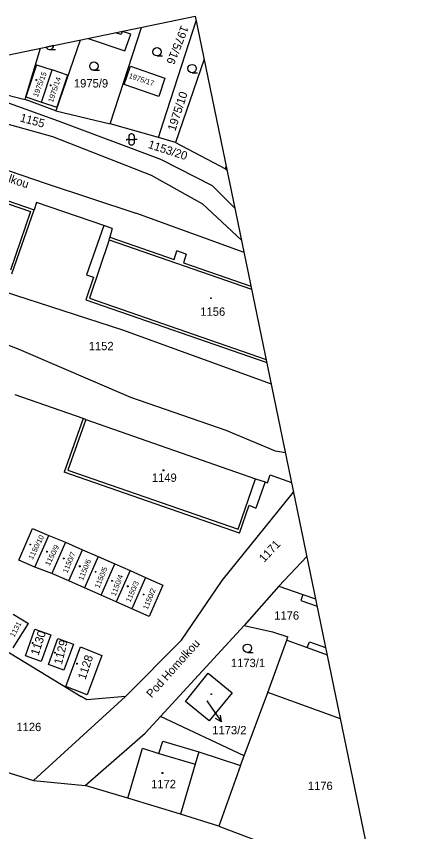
# Model space of a CAD drawing. Extents: x -804166 to -803706, y -1151030 to -1150147.
# Drawn here: x -803907.6 to -803833, y -1150293.8 to -1150147.3 of the extents above; entities that cross this region are included whole.
import ezdxf

# ---------------------------------------------------------------- set-up
doc = ezdxf.new("R2010")
doc.units = 0
for name, color, linetype in [('Default', 7, 'Continuous'), ('formát', 7, 'Continuous'), ('kn_celek - Cisla parcel pomocna', 7, 'Continuous'), ('kn_celek - Cisla pozemkovych parcel', 7, 'Continuous'), ('kn_celek - Cisla stavebnich parcel', 7, 'Continuous'), ('kn_celek - Dalsi prvky mapy popis', 7, 'Continuous'), ('kn_celek - Hranice parcel', 7, 'Continuous'), ('kn_celek - Vnitrni kresby', 7, 'Continuous'), ('kn_celek - Znacky budov', 7, 'Continuous'), ('kn_celek - Znacky kultur', 7, 'Continuous')]:
    doc.layers.add(name, color=color, linetype=linetype)

# ---------------------------------------------------------------- blocks, each defined once
blk = doc.blocks.new('316')
at = {"layer": 'Default'}
for p, q in [((-5, 15.5), (-5, 4.5)), ((0.5, 20), (-0.5, 20)), ((5, 4.5), (5, 15.5)), ((-8.3, 10), (-10, 8.1)), ((-5, 10), (-8.3, 10)), ((-5, 10), (5, 10)), ((-0.5, 0), (0.5, 0)), ((10, 10), (5, 10))]:
    blk.add_line(p, q, dxfattribs=at)
for centre, start, end in [((-0.5, 15.5), 90, 180), ((0.5, 15.5), 0, 90), ((-0.5, 4.5), 180, 270), ((0.5, 4.5), 270, 0)]:
    blk.add_arc(centre, 4.5, start, end, dxfattribs=at)
blk = doc.blocks.new('304')
at = {"layer": 'Default'}
blk.add_line((-0.1, 0), (9.9, 0), dxfattribs=at)
blk.add_circle((-0.1, 7.5), 7.5, dxfattribs=at)
blk = doc.blocks.new('402')
at = {"layer": 'Default'}
for p, q in [((-0.8, 0.8), (0.7, 0.8)), ((-0.8, 0.8), (-0.8, -0.7)), ((0.7, 0.8), (0.7, -0.7)), ((0.7, -0.7), (-0.8, -0.7))]:
    blk.add_line(p, q, dxfattribs=at)
blk = doc.blocks.new('Z61')
at = {"layer": 'Default'}
for p, q in [((0, 0), (30, 0)), ((30, 0), (19.2, 5.3)), ((30, 0), (19.2, -5.3))]:
    blk.add_line(p, q, dxfattribs=at)

msp = doc.modelspace()

# ---------------------------------------------------------------- linework, layer by layer
at = {"layer": 'Default'}
for p, q in [((-803900.82, -1150152.59), (-803902.24, -1150152.88)), ((-803901.57, -1150153.3), (-803900.57, -1150153.3))]:
    msp.add_line(p, q, dxfattribs=at)
msp.add_arc((-803901.57, -1150152.55), 0.75, 206.3406, 356.9897, dxfattribs=at)
at = {"layer": 'formát'}
for p, q in [((-804166.3, -1150207.4), (-803875.43, -1150147.35)), ((-803875.43, -1150147.35), (-803832.97, -1150353.01))]:
    msp.add_line(p, q, dxfattribs=at)
at = {"layer": 'kn_celek - Cisla parcel pomocna'}
msp.add_line((-803873.37, -1150270.26), (-803872.45, -1150271.59), dxfattribs=at)
at = {"layer": 'kn_celek - Hranice parcel'}
for p, q in [((-803881.15, -1150166.28), (-803875.27, -1150148.15)), ((-803890.73, -1150166.65), (-803885.1, -1150149.34)), ((-803887.03, -1150150.53), (-803888.49, -1150150.05)), ((-803888.07, -1150153.56), (-803887.03, -1150150.53)), ((-803896.11, -1150151.62), (-803900.48, -1150164.31)), ((-803894.68, -1150151.32), (-803888.07, -1150153.56)), ((-803904.55, -1150157.46), (-803903.24, -1150153.09)), ((-803873.84, -1150155.07), (-803879, -1150169.98)), ((-803903.93, -1150156.08), (-803905.85, -1150161.82)), ((-803903.93, -1150156.08), (-803901.16, -1150156.99)), ((-803903.08, -1150162.75), (-803901.16, -1150156.99)), ((-803898.39, -1150157.91), (-803901.16, -1150156.99)), ((-803888.2, -1150159.59), (-803887.07, -1150156.33)), ((-803887.07, -1150156.33), (-803880.91, -1150158.47)), ((-803905.85, -1150161.82), (-803904.55, -1150157.46)), ((-803898.39, -1150157.91), (-803900.31, -1150163.68)), ((-803880.91, -1150158.47), (-803881.98, -1150161.74)), ((-803881.98, -1150161.74), (-803888.2, -1150159.59)), ((-803899.99, -1150166.2), (-803915.47, -1150160.65)), ((-803912.36, -1150160.67), (-803906, -1150162.31)), ((-803906, -1150162.31), (-803905.85, -1150161.82)), ((-803900.48, -1150164.31), (-803906, -1150162.31)), ((-803905.85, -1150161.82), (-803903.08, -1150162.75)), ((-803903.08, -1150162.75), (-803900.31, -1150163.68)), ((-803900.48, -1150164.31), (-803890.73, -1150166.65)), ((-803915.16, -1150165.04), (-803901.06, -1150168.96)), ((-803881.62, -1150173.04), (-803899.99, -1150166.2)), ((-803882.07, -1150169.11), (-803890.73, -1150166.65)), ((-803882.07, -1150169.11), (-803881.15, -1150166.28)), ((-803901.06, -1150168.96), (-803883.37, -1150175.87)), ((-803879, -1150169.98), (-803882.07, -1150169.11)), ((-803879, -1150169.98), (-803870, -1150174.71)), ((-803919.23, -1150171.55), (-803902.24, -1150177.36)), ((-803872.35, -1150177.78), (-803881.62, -1150173.04)), ((-803870, -1150174.71), (-803869.87, -1150174.31)), ((-803883.37, -1150175.87), (-803874.13, -1150181)), ((-803870, -1150174.71), (-803869.75, -1150174.89)), ((-803902.24, -1150177.36), (-803886.14, -1150182.73)), ((-803868.32, -1150181.79), (-803872.35, -1150177.78)), ((-803912.9, -1150179.16), (-803904.38, -1150182.12)), ((-803903.94, -1150180.77), (-803904.38, -1150182.12)), ((-803891.87, -1150184.92), (-803903.94, -1150180.77)), ((-803874.13, -1150181), (-803867.13, -1150187.56)), ((-803908.4, -1150193.58), (-803904.38, -1150182.12)), ((-803866.67, -1150189.78), (-803886.14, -1150182.73)), ((-803891.87, -1150184.92), (-803894.99, -1150193.77)), ((-803890.34, -1150185.46), (-803891.87, -1150184.92)), ((-803890.34, -1150185.46), (-803890.78, -1150187.03)), ((-803890.78, -1150187.03), (-803879.25, -1150191.02)), ((-803879.25, -1150191.02), (-803878.76, -1150189.48)), ((-803877.06, -1150190.07), (-803878.76, -1150189.48)), ((-803877.06, -1150190.07), (-803877.56, -1150191.6)), ((-803877.56, -1150191.6), (-803865.43, -1150195.8)), ((-803893.69, -1150194.21), (-803895.12, -1150198.28)), ((-803894.99, -1150193.77), (-803893.69, -1150194.21)), ((-803907.04, -1150207.19), (-803936.79, -1150195.65)), ((-803909.95, -1150196.71), (-803888.51, -1150203.65)), ((-803895.12, -1150198.28), (-803862.59, -1150209.54)), ((-803888.51, -1150203.65), (-803861.8, -1150213.36)), ((-803887.03, -1150215.78), (-803907.04, -1150207.19)), ((-803895.6, -1150219.58), (-803907.76, -1150215.33)), ((-803869.9, -1150221.72), (-803887.03, -1150215.78)), ((-803895.6, -1150219.58), (-803898.96, -1150229.23)), ((-803895.12, -1150219.75), (-803895.6, -1150219.58)), ((-803895.12, -1150219.75), (-803864.59, -1150230.39)), ((-803861.03, -1150225.43), (-803869.9, -1150221.72)), ((-803859.25, -1150225.72), (-803861.03, -1150225.43)), ((-803867.5, -1150240.16), (-803898.96, -1150229.23)), ((-803862.45, -1150231.1), (-803861.96, -1150229.72)), ((-803861.96, -1150229.72), (-803858.15, -1150231.05)), ((-803864.59, -1150230.39), (-803862.9, -1150230.95)), ((-803862.9, -1150230.95), (-803864.54, -1150235.66)), ((-803862.9, -1150230.95), (-803862.45, -1150231.1)), ((-803870.63, -1150248.69), (-803857.79, -1150232.8)), ((-803867.5, -1150240.16), (-803865.74, -1150235.12)), ((-803865.74, -1150235.12), (-803864.54, -1150235.66)), ((-803907.14, -1150244.99), (-803904.65, -1150239.3)), ((-803904.65, -1150239.3), (-803901.77, -1150240.6)), ((-803904.26, -1150246.27), (-803901.77, -1150240.6)), ((-803901.77, -1150240.6), (-803898.77, -1150241.78)), ((-803898.77, -1150241.78), (-803901.18, -1150247.39)), ((-803898.77, -1150241.78), (-803895.71, -1150243.13)), ((-803898.17, -1150248.72), (-803895.71, -1150243.13)), ((-803895.71, -1150243.13), (-803892.87, -1150244.37)), ((-803892.87, -1150244.37), (-803895.33, -1150249.98)), ((-803892.87, -1150244.37), (-803889.9, -1150245.68)), ((-803860.43, -1150249.7), (-803855.41, -1150244.35)), ((-803904.26, -1150246.27), (-803907.14, -1150244.99)), ((-803901.18, -1150247.39), (-803904.26, -1150246.27)), ((-803892.37, -1150251.29), (-803889.9, -1150245.68)), ((-803889.9, -1150245.68), (-803887.16, -1150246.89)), ((-803898.17, -1150248.72), (-803901.18, -1150247.39)), ((-803887.16, -1150246.89), (-803889.62, -1150252.51)), ((-803887.16, -1150246.89), (-803884.36, -1150248.11)), ((-803895.33, -1150249.98), (-803898.17, -1150248.72)), ((-803884.36, -1150248.11), (-803886.83, -1150253.75)), ((-803884.36, -1150248.11), (-803881.25, -1150249.49)), ((-803877.93, -1150259.4), (-803870.63, -1150248.69)), ((-803892.37, -1150251.29), (-803895.33, -1150249.98)), ((-803881.25, -1150249.49), (-803883.72, -1150255.11)), ((-803860.43, -1150249.7), (-803866.67, -1150256.73)), ((-803860.43, -1150249.7), (-803856.1, -1150251.19)), ((-803889.62, -1150252.51), (-803892.37, -1150251.29)), ((-803856.1, -1150251.19), (-803856.47, -1150252.28)), ((-803886.83, -1150253.75), (-803889.62, -1150252.51)), ((-803856.47, -1150252.28), (-803853.56, -1150253.27)), ((-803908.17, -1150254.71), (-803905.37, -1150256.41)), ((-803883.72, -1150255.11), (-803886.83, -1150253.75)), ((-803908.13, -1150260.76), (-803905.37, -1150256.41)), ((-803916.86, -1150256.8), (-803895.91, -1150269.48)), ((-803905.91, -1150262.21), (-803904.24, -1150257.41)), ((-803904.24, -1150257.41), (-803901.39, -1150258.44)), ((-803881.7, -1150273.09), (-803866.67, -1150256.73)), ((-803866.67, -1150256.73), (-803861.59, -1150257.9)), ((-803861.59, -1150257.9), (-803858.81, -1150258.78)), ((-803901.39, -1150258.44), (-803903.13, -1150263.19)), ((-803901.78, -1150263.76), (-803900.12, -1150259.06)), ((-803900.12, -1150259.06), (-803897.31, -1150260.08)), ((-803888, -1150269.48), (-803877.93, -1150259.4)), ((-803862.41, -1150268.75), (-803858.98, -1150259.36)), ((-803858.98, -1150259.36), (-803858.81, -1150258.78)), ((-803858.98, -1150259.36), (-803855.32, -1150260.7)), ((-803897.31, -1150260.08), (-803899.02, -1150264.79)), ((-803898.69, -1150267.68), (-803896.04, -1150260.6)), ((-803896.04, -1150260.6), (-803892.24, -1150262.13)), ((-803855.32, -1150260.7), (-803854.92, -1150259.66)), ((-803854.92, -1150259.66), (-803852.03, -1150260.7)), ((-803903.13, -1150263.19), (-803905.91, -1150262.21)), ((-803892.24, -1150262.13), (-803894.87, -1150269.18)), ((-803899.02, -1150264.79), (-803901.78, -1150263.76)), ((-803877.21, -1150270.37), (-803873.13, -1150265.29)), ((-803873.13, -1150265.29), (-803868.81, -1150268.81)), ((-803894.87, -1150269.18), (-803898.69, -1150267.68)), ((-803904.51, -1150284.6), (-803888, -1150269.48)), ((-803894.93, -1150270.07), (-803895.91, -1150269.48)), ((-803888, -1150269.48), (-803894.93, -1150270.07)), ((-803868.81, -1150268.81), (-803872.95, -1150273.85)), ((-803866.65, -1150280.13), (-803862.41, -1150268.75)), ((-803849.38, -1150273.52), (-803862.41, -1150268.75)), ((-803872.95, -1150273.85), (-803877.21, -1150270.37)), ((-803884.43, -1150276.06), (-803881.7, -1150273.09)), ((-803866.65, -1150280.13), (-803881.7, -1150273.09)), ((-803895.24, -1150285.5), (-803884.43, -1150276.06)), ((-803917.94, -1150280.35), (-803904.51, -1150284.6)), ((-803867.31, -1150281.9), (-803866.65, -1150280.13)), ((-803867.31, -1150281.9), (-803871.21, -1150292.78)), ((-803904.51, -1150284.6), (-803895.24, -1150285.5)), ((-803887.57, -1150287.75), (-803895.24, -1150285.5)), ((-803878.12, -1150290.61), (-803887.57, -1150287.75)), ((-803871.21, -1150292.78), (-803878.12, -1150290.61)), ((-803871.21, -1150292.78), (-803843.78, -1150303.13))]:
    msp.add_line(p, q, dxfattribs=at)
at = {"layer": 'kn_celek - Vnitrni kresby'}
for p, q in [((-803888.74, -1150150.6), (-803889.68, -1150150.29)), ((-803888.55, -1150150.06), (-803888.74, -1150150.6)), ((-803922.71, -1150176.27), (-803905.04, -1150182.42)), ((-803905.04, -1150182.42), (-803908.64, -1150192.92)), ((-803890.92, -1150187.51), (-803894.43, -1150197.99)), ((-803890.92, -1150187.51), (-803890.78, -1150187.03)), ((-803890.92, -1150187.51), (-803865.31, -1150196.37)), ((-803894.43, -1150197.99), (-803862.71, -1150208.99)), ((-803895.12, -1150219.75), (-803898.3, -1150228.84)), ((-803898.3, -1150228.84), (-803867.76, -1150239.45)), ((-803867.76, -1150239.45), (-803864.59, -1150230.39)), ((-803856.1, -1150251.19), (-803853.83, -1150251.96)), ((-803855.32, -1150260.7), (-803851.76, -1150262.01)), ((-803881.99, -1150279.74), (-803881.29, -1150277.51)), ((-803881.29, -1150277.51), (-803874.81, -1150279.44)), ((-803887.57, -1150287.75), (-803884.9, -1150278.8)), ((-803884.9, -1150278.8), (-803881.99, -1150279.74)), ((-803881.99, -1150279.74), (-803875.47, -1150281.66)), ((-803874.81, -1150279.44), (-803875.47, -1150281.66)), ((-803874.81, -1150279.44), (-803867.31, -1150281.9)), ((-803875.47, -1150281.66), (-803878.12, -1150290.61))]:
    msp.add_line(p, q, dxfattribs=at)

# ---------------------------------------------------------------- block references
at = {"layer": 'kn_celek - Cisla parcel pomocna', "xscale": 0.1, "yscale": 0.10000000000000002, "rotation": -55.312649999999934}
msp.add_blockref('Z61', (-803872.45, -1150271.59), dxfattribs=at)
at = {"layer": 'kn_celek - Znacky budov', "xscale": 0.1, "yscale": 0.10000000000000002}
for p in [(-803904.02, -1150158.8), (-803901.43, -1150159.75), (-803872.65, -1150197.97), (-803881.16, -1150228.9), (-803905.1, -1150242.2), (-803902.1, -1150243.49), (-803899.08, -1150244.73), (-803896.19, -1150246.14), (-803893.36, -1150247.11), (-803890.38, -1150248.73), (-803887.57, -1150249.71), (-803884.74, -1150251.18), (-803904.66, -1150259.9), (-803900.65, -1150261.62), (-803896.71, -1150263.61), (-803872.59, -1150269.09), (-803881.36, -1150283.23)]:
    msp.add_blockref('402', p, dxfattribs=at)
at = {"layer": 'kn_celek - Znacky kultur', "xscale": 0.1, "yscale": 0.10000000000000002}
for name, p in [('304', (-803882.3, -1150154.47)), ('304', (-803893.64, -1150157.05)), ('304', (-803876, -1150157.48)), ('316', (-803886.88, -1150170.45)), ('304', (-803866.05, -1150261.58))]:
    msp.add_blockref(name, p, dxfattribs=at)

# ---------------------------------------------------------------- texts
at = {"layer": 'kn_celek - Cisla parcel pomocna'}
msp.add_text('1173/2', height=1.5, dxfattribs=at).set_placement((-803872.38, -1150276.29))
at = {"layer": 'kn_celek - Cisla pozemkovych parcel'}
for s, height, rotation, p in [('1975/16', 1.5, 248.2097, (-803877.96, -1150148.87)), ('1975/17', 0.94, 342.0721, (-803887.47, -1150158.42)), ('1975/10', 1.5, 72, (-803879.03, -1150168.07)), ('1155', 1.5, 344.7, (-803907.03, -1150166.2)), ('1153/20', 1.5, 342, (-803884.04, -1150170.96)), ('1171', 1.5, 46.8, (-803863.07, -1150245.52))]:
    msp.add_text(s, height=height, rotation=rotation, dxfattribs=at).set_placement(p)
for s, p in [('1975/9', (-803897.23, -1150160.13)), ('1152', (-803894.57, -1150207.31)), ('1176', (-803861.25, -1150255.7)), ('1173/1', (-803869.04, -1150264.22)), ('1126', (-803907.56, -1150275.71)), ('1176', (-803855.21, -1150286.29))]:
    msp.add_text(s, height=1.5, dxfattribs=at).set_placement(p)
at = {"layer": 'kn_celek - Cisla stavebnich parcel'}
for s, height, rotation, p in [('1975/15', 0.94, 69.444, (-803903.74, -1150161.93)), ('1975/14', 0.94, 71.3505, (-803901.02, -1150162.89)), ('1150/10', 0.94, 63.435, (-803904.65, -1150244.99)), ('1150/9', 0.94, 63.435, (-803901.63, -1150246.13)), ('1150/7', 0.94, 67.3801, (-803898.43, -1150247.43)), ('1150/6', 0.94, 67.7673, (-803895.62, -1150248.74)), ('1150/5', 0.94, 67.6199, (-803892.69, -1150250.13)), ('1150/4', 0.94, 69.444, (-803889.76, -1150251.55)), ('1150/3', 0.94, 66.1941, (-803887.12, -1150252.66)), ('1150/2', 0.94, 67.751, (-803884.01, -1150253.98)), ('1131', 0.94, 62.1027, (-803907.97, -1150258.93)), ('1130', 1.5, 71.565, (-803903.63, -1150262.24)), ('1129', 1.5, 75.9638, (-803899.41, -1150263.87)), ('1128', 1.5, 71.565, (-803895.17, -1150266.58))]:
    msp.add_text(s, height=height, rotation=rotation, dxfattribs=at).set_placement(p)
for s, height, p in [('1156', 1.5, (-803874.53, -1150201.13)), ('1149', 1.5, (-803883.23, -1150230.95)), ('1173/2', 0.1, (-803873.37, -1150270.23)), ('1172', 1.5, (-803883.37, -1150285.97))]:
    msp.add_text(s, height=height, dxfattribs=at).set_placement(p)
at = {"layer": 'kn_celek - Dalsi prvky mapy popis'}
for rotation, p in [(341.7816, (-803918.12, -1150174.15)), (48.1582, (-803883.27, -1150269.85))]:
    msp.add_text('Pod Homolkou', height=1.5, rotation=rotation, dxfattribs=at).set_placement(p)

doc.saveas('drawing.dxf')
